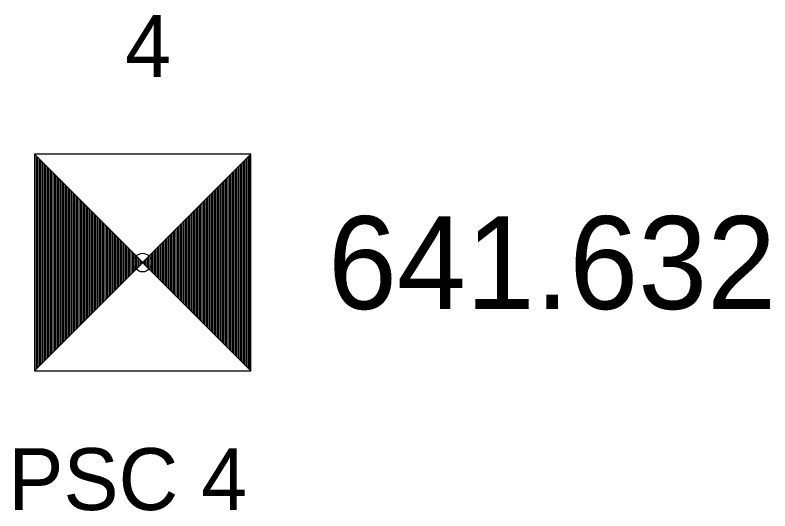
# Model space of a CAD drawing. Extents: x 1529475 to 1532053, y 876698 to 877911.
# Drawn here: x 1529647.17 to 1529659.39, y 877545.6 to 877553.62 of the extents above; entities that cross this region are included whole.
import ezdxf

# ---------------------------------------------------------------- set-up
doc = ezdxf.new("R2010")
doc.units = 0
for name, color, linetype in [('RD_HC_Survey', 7, 'Continuous'), ('RD_HC_Survey_ELEV', 7, 'Continuous'), ('RD_HC_txCode', 7, 'Continuous'), ('RD_SMD_Locator', 7, 'Continuous')]:
    doc.layers.add(name, color=color, linetype=linetype)

msp = doc.modelspace()

# ---------------------------------------------------------------- linework, layer by layer
at = {"layer": 'RD_HC_Survey'}
for p, q in [((1529647.487, 877551.367), (1529650.987, 877547.867)), ((1529650.987, 877551.367), (1529647.487, 877547.867)), ((1529647.512, 877551.343), (1529647.512, 877547.892)), ((1529647.537, 877551.318), (1529647.537, 877547.917)), ((1529647.561, 877551.293), (1529647.561, 877547.942)), ((1529650.913, 877551.293), (1529650.913, 877547.942)), ((1529650.938, 877551.318), (1529650.938, 877547.917)), ((1529650.962, 877551.343), (1529650.962, 877547.892)), ((1529647.586, 877551.268), (1529647.586, 877547.966)), ((1529647.611, 877551.244), (1529647.611, 877547.991)), ((1529647.636, 877551.219), (1529647.636, 877548.016)), ((1529647.66, 877551.194), (1529647.66, 877548.041)), ((1529647.685, 877551.169), (1529647.685, 877548.065)), ((1529650.789, 877551.169), (1529650.789, 877548.065)), ((1529650.814, 877551.194), (1529650.814, 877548.041)), ((1529650.839, 877551.219), (1529650.839, 877548.016)), ((1529650.863, 877551.244), (1529650.863, 877547.991)), ((1529650.888, 877551.268), (1529650.888, 877547.966)), ((1529647.71, 877551.145), (1529647.71, 877548.09)), ((1529647.735, 877551.12), (1529647.735, 877548.115)), ((1529647.759, 877551.095), (1529647.759, 877548.14)), ((1529647.784, 877551.07), (1529647.784, 877548.164)), ((1529647.809, 877551.046), (1529647.809, 877548.189)), ((1529650.665, 877551.046), (1529650.665, 877548.189)), ((1529650.69, 877551.07), (1529650.69, 877548.164)), ((1529650.715, 877551.095), (1529650.715, 877548.14)), ((1529650.74, 877551.12), (1529650.74, 877548.115)), ((1529650.764, 877551.145), (1529650.764, 877548.09)), ((1529647.834, 877551.021), (1529647.834, 877548.214)), ((1529647.858, 877550.996), (1529647.858, 877548.239)), ((1529647.883, 877550.971), (1529647.883, 877548.263)), ((1529647.908, 877550.947), (1529647.908, 877548.288)), ((1529647.933, 877550.922), (1529647.933, 877548.313)), ((1529650.542, 877550.922), (1529650.542, 877548.313)), ((1529650.566, 877550.947), (1529650.566, 877548.288)), ((1529650.591, 877550.971), (1529650.591, 877548.263)), ((1529650.616, 877550.996), (1529650.616, 877548.239)), ((1529650.641, 877551.021), (1529650.641, 877548.214)), ((1529647.957, 877550.897), (1529647.957, 877548.338)), ((1529647.982, 877550.872), (1529647.982, 877548.362)), ((1529648.007, 877550.848), (1529648.007, 877548.387)), ((1529648.032, 877550.823), (1529648.032, 877548.412)), ((1529648.056, 877550.798), (1529648.056, 877548.437)), ((1529650.418, 877550.798), (1529650.418, 877548.437)), ((1529650.443, 877550.823), (1529650.443, 877548.412)), ((1529650.467, 877550.848), (1529650.467, 877548.387)), ((1529650.492, 877550.872), (1529650.492, 877548.362)), ((1529650.517, 877550.897), (1529650.517, 877548.338)), ((1529648.081, 877550.773), (1529648.081, 877548.461)), ((1529648.106, 877550.749), (1529648.106, 877548.486)), ((1529648.131, 877550.724), (1529648.131, 877548.511)), ((1529648.155, 877550.699), (1529648.155, 877548.536)), ((1529648.18, 877550.674), (1529648.18, 877548.56)), ((1529650.294, 877550.674), (1529650.294, 877548.56)), ((1529650.319, 877550.699), (1529650.319, 877548.536)), ((1529650.344, 877550.724), (1529650.344, 877548.511)), ((1529650.368, 877550.749), (1529650.368, 877548.486)), ((1529650.393, 877550.773), (1529650.393, 877548.461)), ((1529648.205, 877550.65), (1529648.205, 877548.585)), ((1529648.23, 877550.625), (1529648.23, 877548.61)), ((1529648.254, 877550.6), (1529648.254, 877548.635)), ((1529648.279, 877550.575), (1529648.279, 877548.659)), ((1529648.304, 877550.551), (1529648.304, 877548.684)), ((1529650.17, 877550.551), (1529650.17, 877548.684)), ((1529650.195, 877550.575), (1529650.195, 877548.659)), ((1529650.22, 877550.6), (1529650.22, 877548.635)), ((1529650.245, 877550.625), (1529650.245, 877548.61)), ((1529650.269, 877550.65), (1529650.269, 877548.585)), ((1529648.329, 877550.526), (1529648.329, 877548.709)), ((1529648.353, 877550.501), (1529648.353, 877548.734)), ((1529648.378, 877550.476), (1529648.378, 877548.758)), ((1529648.403, 877550.452), (1529648.403, 877548.783)), ((1529650.071, 877550.452), (1529650.071, 877548.783)), ((1529650.096, 877550.476), (1529650.096, 877548.758)), ((1529650.121, 877550.501), (1529650.121, 877548.734)), ((1529650.146, 877550.526), (1529650.146, 877548.709)), ((1529648.428, 877550.427), (1529648.428, 877548.808)), ((1529648.452, 877550.402), (1529648.452, 877548.833)), ((1529648.477, 877550.377), (1529648.477, 877548.857)), ((1529648.502, 877550.353), (1529648.502, 877548.882)), ((1529648.527, 877550.328), (1529648.527, 877548.907)), ((1529649.948, 877550.328), (1529649.948, 877548.907)), ((1529649.972, 877550.353), (1529649.972, 877548.882)), ((1529649.997, 877550.377), (1529649.997, 877548.857)), ((1529650.022, 877550.402), (1529650.022, 877548.833)), ((1529650.047, 877550.427), (1529650.047, 877548.808)), ((1529648.551, 877550.303), (1529648.551, 877548.931)), ((1529648.576, 877550.278), (1529648.576, 877548.956)), ((1529648.601, 877550.254), (1529648.601, 877548.981)), ((1529648.626, 877550.229), (1529648.626, 877549.006)), ((1529648.65, 877550.204), (1529648.65, 877549.03)), ((1529649.824, 877550.204), (1529649.824, 877549.03)), ((1529649.849, 877550.229), (1529649.849, 877549.006)), ((1529649.874, 877550.254), (1529649.874, 877548.981)), ((1529649.898, 877550.278), (1529649.898, 877548.956)), ((1529649.923, 877550.303), (1529649.923, 877548.931)), ((1529648.675, 877550.179), (1529648.675, 877549.055)), ((1529648.7, 877550.155), (1529648.7, 877549.08)), ((1529648.725, 877550.13), (1529648.725, 877549.105)), ((1529648.749, 877550.105), (1529648.749, 877549.129)), ((1529648.774, 877550.08), (1529648.774, 877549.154)), ((1529649.7, 877550.08), (1529649.7, 877549.154)), ((1529649.725, 877550.105), (1529649.725, 877549.129)), ((1529649.75, 877550.13), (1529649.75, 877549.105)), ((1529649.775, 877550.155), (1529649.775, 877549.08)), ((1529649.799, 877550.179), (1529649.799, 877549.055)), ((1529648.799, 877550.056), (1529648.799, 877549.179)), ((1529648.824, 877550.031), (1529648.824, 877549.204)), ((1529648.848, 877550.006), (1529648.848, 877549.228)), ((1529648.873, 877549.981), (1529648.873, 877549.253)), ((1529648.898, 877549.957), (1529648.898, 877549.278)), ((1529649.577, 877549.957), (1529649.577, 877549.278)), ((1529649.601, 877549.981), (1529649.601, 877549.253)), ((1529649.626, 877550.006), (1529649.626, 877549.228)), ((1529649.651, 877550.031), (1529649.651, 877549.204)), ((1529649.676, 877550.056), (1529649.676, 877549.179)), ((1529648.923, 877549.932), (1529648.923, 877549.303)), ((1529648.947, 877549.907), (1529648.947, 877549.327)), ((1529648.972, 877549.882), (1529648.972, 877549.352)), ((1529648.997, 877549.858), (1529648.997, 877549.377)), ((1529649.022, 877549.833), (1529649.022, 877549.402)), ((1529649.453, 877549.833), (1529649.453, 877549.402)), ((1529649.478, 877549.858), (1529649.478, 877549.377)), ((1529649.502, 877549.882), (1529649.502, 877549.352)), ((1529649.527, 877549.907), (1529649.527, 877549.327)), ((1529649.552, 877549.932), (1529649.552, 877549.303)), ((1529649.046, 877549.808), (1529649.046, 877549.426)), ((1529649.071, 877549.783), (1529649.071, 877549.451)), ((1529649.096, 877549.759), (1529649.096, 877549.476)), ((1529649.121, 877549.734), (1529649.121, 877549.501)), ((1529649.145, 877549.709), (1529649.145, 877549.525)), ((1529649.329, 877549.709), (1529649.329, 877549.525)), ((1529649.354, 877549.734), (1529649.354, 877549.501)), ((1529649.379, 877549.759), (1529649.379, 877549.476)), ((1529649.403, 877549.783), (1529649.403, 877549.451)), ((1529649.428, 877549.808), (1529649.428, 877549.426)), ((1529649.17, 877549.684), (1529649.17, 877549.55)), ((1529649.195, 877549.66), (1529649.195, 877549.575)), ((1529649.22, 877549.635), (1529649.22, 877549.6)), ((1529649.255, 877549.635), (1529649.255, 877549.6)), ((1529649.28, 877549.66), (1529649.28, 877549.575)), ((1529649.304, 877549.684), (1529649.304, 877549.55))]:
    msp.add_line(p, q, dxfattribs=at)
msp.add_lwpolyline([(1529650.987, 877551.367), (1529647.487, 877551.367), (1529647.487, 877547.867), (1529650.987, 877547.867)], close=True, dxfattribs=at)
at = {"layer": 'RD_SMD_Locator'}
msp.add_circle((1529649.237, 877549.617), 0.15, dxfattribs=at)

# ---------------------------------------------------------------- texts
at = {"layer": 'RD_HC_Survey_ELEV'}
msp.add_text('641.632', height=1.5, dxfattribs=at).set_placement((1529652.237, 877548.867))
at = {"layer": 'RD_HC_txCode'}
for s, p in [('4', (1529648.954, 877552.617)), ('PSC 4', (1529647.064, 877545.617))]:
    msp.add_text(s, height=1, dxfattribs=at).set_placement(p)

doc.saveas('drawing.dxf')
